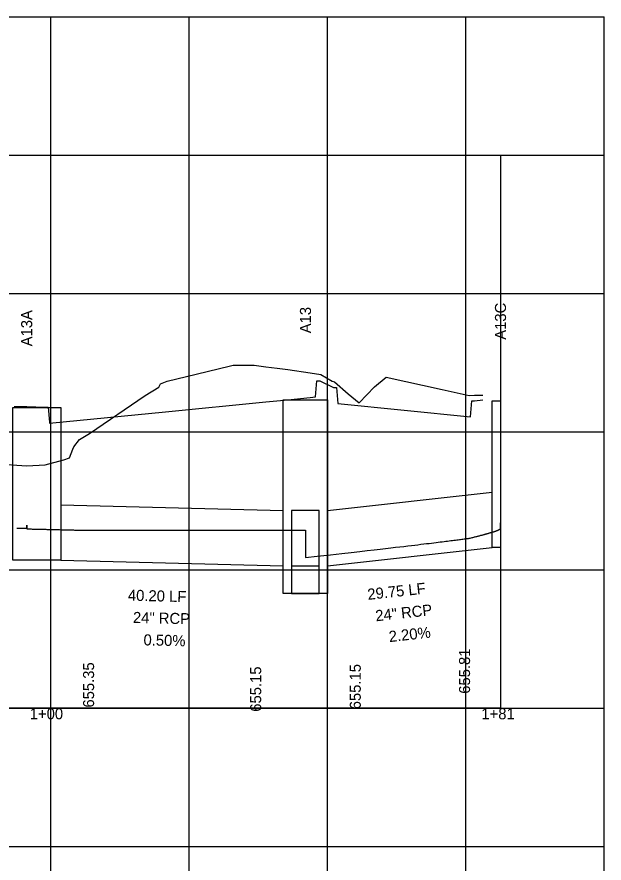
# Model space of a CAD drawing. Extents: x 2252703 to 2264864, y 13787568 to 13790989.
# Drawn here: x 2264657.5 to 2264763.7, y 13789162.9 to 13789315.9 of the extents above; entities that cross this region are included whole.
import ezdxf

# ---------------------------------------------------------------- set-up
doc = ezdxf.new("R2010")
doc.units = 0
for name, color, linetype in [('blank4', 7, 'Continuous'), ('BORD_grid_bottom_major_5int', 7, 'Continuous'), ('D_DRN_PROF_HGL', 7, 'Continuous'), ('D_PROF_1', 7, 'Continuous'), ('D_PROF_NOTES_1', 7, 'Continuous'), ('Default', 7, 'Continuous'), ('Drain_PipeInside', 7, 'Continuous'), ('E_Terrain', 7, 'Continuous'), ('Inlet', 7, 'Continuous'), ('z - Construction', 7, 'Continuous')]:
    doc.layers.add(name, color=color, linetype=linetype)

msp = doc.modelspace()

# ---------------------------------------------------------------- linework, layer by layer
at = {"layer": 'blank4'}
msp.add_lwpolyline([(2264563.67, 13789190.93), (2264563.67, 13789290.93), (2264744.95, 13789290.93), (2264744.95, 13789190.93)], close=True, dxfattribs=at)
at = {"layer": 'BORD_grid_bottom_major_5int'}
for p, q in [((2264413.67, 13789315.93), (2264763.67, 13789315.93)), ((2264663.67, 13789015.93), (2264663.67, 13789315.93)), ((2264688.67, 13789015.93), (2264688.67, 13789315.93)), ((2264713.67, 13789015.93), (2264713.67, 13789315.93)), ((2264738.67, 13789015.93), (2264738.67, 13789315.93)), ((2264763.67, 13789015.93), (2264763.67, 13789315.93)), ((2264413.67, 13789290.93), (2264763.67, 13789290.93)), ((2264413.67, 13789265.93), (2264763.67, 13789265.93)), ((2264413.67, 13789240.93), (2264763.67, 13789240.93)), ((2264413.67, 13789215.93), (2264763.67, 13789215.93)), ((2264413.67, 13789190.93), (2264763.67, 13789190.93)), ((2264413.67, 13789165.93), (2264763.67, 13789165.93))]:
    msp.add_line(p, q, dxfattribs=at)
at = {"layer": 'D_DRN_PROF_HGL'}
for p, q in [((2264659.31, 13789223.51), (2264659.31, 13789224.02)), ((2264709.7, 13789223.13), (2264709.7, 13789218.18))]:
    msp.add_line(p, q, dxfattribs=at)
for points in [[(2264657.53, 13789223.51), (2264657.73, 13789223.51), (2264657.93, 13789223.51), (2264658.12, 13789223.51), (2264658.32, 13789223.51), (2264658.52, 13789223.51), (2264658.72, 13789223.51), (2264658.92, 13789223.51), (2264659.12, 13789223.51), (2264659.31, 13789223.51)], [(2264659.31, 13789224.02), (2264659.31, 13789223.35), (2264659.35, 13789223.36), (2264659.54, 13789223.35), (2264659.73, 13789223.35), (2264659.92, 13789223.34), (2264660.11, 13789223.34), (2264660.3, 13789223.33), (2264660.49, 13789223.33), (2264660.68, 13789223.33), (2264660.87, 13789223.32), (2264661.06, 13789223.32), (2264661.25, 13789223.31), (2264661.44, 13789223.31), (2264661.63, 13789223.3), (2264661.82, 13789223.3), (2264662.02, 13789223.29), (2264662.21, 13789223.29), (2264662.4, 13789223.28), (2264662.59, 13789223.28), (2264662.78, 13789223.28), (2264662.97, 13789223.27), (2264663.16, 13789223.27), (2264663.35, 13789223.26), (2264663.55, 13789223.26), (2264663.74, 13789223.25), (2264663.93, 13789223.25), (2264664.12, 13789223.24), (2264664.31, 13789223.24), (2264664.51, 13789223.23), (2264664.7, 13789223.23), (2264664.89, 13789223.22), (2264665.08, 13789223.22), (2264665.27, 13789223.22), (2264665.47, 13789223.21), (2264665.66, 13789223.21), (2264665.85, 13789223.2), (2264666.04, 13789223.2), (2264666.24, 13789223.19), (2264666.43, 13789223.19), (2264666.62, 13789223.18), (2264666.81, 13789223.18), (2264667.01, 13789223.17), (2264667.2, 13789223.17), (2264667.39, 13789223.16), (2264667.58, 13789223.16), (2264667.78, 13789223.16), (2264667.97, 13789223.15), (2264668.16, 13789223.15), (2264668.36, 13789223.14), (2264668.55, 13789223.14), (2264668.74, 13789223.13), (2264668.93, 13789223.13), (2264669.13, 13789223.12), (2264669.32, 13789223.12), (2264669.51, 13789223.11), (2264669.71, 13789223.11), (2264669.9, 13789223.11), (2264670.09, 13789223.11), (2264670.29, 13789223.11), (2264670.48, 13789223.11), (2264670.68, 13789223.11), (2264670.87, 13789223.11), (2264671.06, 13789223.12), (2264671.26, 13789223.12), (2264671.45, 13789223.12), (2264671.64, 13789223.12), (2264671.84, 13789223.12), (2264672.03, 13789223.12), (2264672.23, 13789223.12), (2264672.42, 13789223.12), (2264672.61, 13789223.12), (2264672.81, 13789223.12), (2264673, 13789223.12), (2264673.2, 13789223.12), (2264673.39, 13789223.12), (2264673.58, 13789223.12), (2264673.78, 13789223.12), (2264673.97, 13789223.12), (2264674.17, 13789223.12), (2264674.36, 13789223.12), (2264674.56, 13789223.12), (2264674.75, 13789223.12), (2264674.95, 13789223.12), (2264675.14, 13789223.12), (2264675.34, 13789223.12), (2264675.53, 13789223.12), (2264675.72, 13789223.12), (2264675.92, 13789223.12), (2264676.11, 13789223.12), (2264676.31, 13789223.12), (2264676.5, 13789223.12), (2264676.7, 13789223.12), (2264676.89, 13789223.12), (2264677.09, 13789223.12), (2264677.28, 13789223.12), (2264677.48, 13789223.12), (2264677.67, 13789223.12), (2264677.87, 13789223.12), (2264678.07, 13789223.12), (2264678.26, 13789223.12), (2264678.46, 13789223.12), (2264678.65, 13789223.12), (2264678.85, 13789223.12), (2264679.04, 13789223.12), (2264679.24, 13789223.12), (2264679.43, 13789223.12), (2264679.63, 13789223.12), (2264679.82, 13789223.12), (2264680.02, 13789223.12), (2264680.22, 13789223.12), (2264680.41, 13789223.12), (2264680.61, 13789223.12), (2264680.8, 13789223.12), (2264681, 13789223.12), (2264681.19, 13789223.12), (2264681.39, 13789223.12), (2264681.59, 13789223.12), (2264681.78, 13789223.12), (2264681.98, 13789223.12), (2264682.17, 13789223.12), (2264682.37, 13789223.12), (2264682.57, 13789223.12), (2264682.76, 13789223.12), (2264682.96, 13789223.12), (2264683.15, 13789223.12), (2264683.35, 13789223.12), (2264683.55, 13789223.12), (2264683.74, 13789223.12), (2264683.94, 13789223.12), (2264684.14, 13789223.12), (2264684.33, 13789223.12), (2264684.53, 13789223.12), (2264684.73, 13789223.12), (2264684.92, 13789223.12), (2264685.12, 13789223.12), (2264685.32, 13789223.12), (2264685.51, 13789223.12), (2264685.71, 13789223.12), (2264685.91, 13789223.12), (2264686.1, 13789223.12), (2264686.3, 13789223.12), (2264686.5, 13789223.12), (2264686.69, 13789223.12), (2264686.89, 13789223.12), (2264687.09, 13789223.12), (2264687.28, 13789223.12), (2264687.48, 13789223.12), (2264687.68, 13789223.12), (2264687.87, 13789223.12), (2264688.07, 13789223.12), (2264688.27, 13789223.12), (2264688.46, 13789223.12), (2264688.66, 13789223.12), (2264688.86, 13789223.12), (2264689.06, 13789223.12), (2264689.25, 13789223.12), (2264689.45, 13789223.13), (2264689.65, 13789223.13), (2264689.84, 13789223.13), (2264690.04, 13789223.13), (2264690.24, 13789223.13), (2264690.44, 13789223.13), (2264690.63, 13789223.13), (2264690.83, 13789223.13), (2264691.03, 13789223.13), (2264691.23, 13789223.13), (2264691.42, 13789223.13), (2264691.62, 13789223.13), (2264691.82, 13789223.13), (2264692.02, 13789223.13), (2264692.21, 13789223.13), (2264692.41, 13789223.13), (2264692.61, 13789223.13), (2264692.81, 13789223.13), (2264693.01, 13789223.13), (2264693.2, 13789223.13), (2264693.4, 13789223.13), (2264693.6, 13789223.13), (2264693.8, 13789223.13), (2264693.99, 13789223.13), (2264694.19, 13789223.13), (2264694.39, 13789223.13), (2264694.59, 13789223.13), (2264694.79, 13789223.13), (2264694.98, 13789223.13), (2264695.18, 13789223.13), (2264695.38, 13789223.13), (2264695.58, 13789223.13), (2264695.78, 13789223.13), (2264695.97, 13789223.13), (2264696.17, 13789223.13), (2264696.37, 13789223.13), (2264696.57, 13789223.13), (2264696.77, 13789223.13), (2264696.97, 13789223.13), (2264697.16, 13789223.13), (2264697.36, 13789223.13), (2264697.56, 13789223.13), (2264697.76, 13789223.13), (2264697.96, 13789223.13), (2264698.15, 13789223.13), (2264698.35, 13789223.13), (2264698.55, 13789223.13), (2264698.75, 13789223.13), (2264698.95, 13789223.13), (2264699.15, 13789223.13), (2264699.35, 13789223.13), (2264699.54, 13789223.13), (2264699.74, 13789223.13), (2264699.94, 13789223.13), (2264700.14, 13789223.13), (2264700.34, 13789223.13), (2264700.54, 13789223.13), (2264700.74, 13789223.13), (2264700.93, 13789223.13), (2264701.13, 13789223.13), (2264701.33, 13789223.13), (2264701.53, 13789223.13), (2264701.73, 13789223.13), (2264701.93, 13789223.13), (2264702.13, 13789223.13), (2264702.33, 13789223.13), (2264702.53, 13789223.13), (2264702.72, 13789223.13), (2264702.92, 13789223.13), (2264703.12, 13789223.13), (2264703.32, 13789223.13), (2264703.52, 13789223.13), (2264703.72, 13789223.13), (2264703.92, 13789223.13), (2264704.12, 13789223.13), (2264704.32, 13789223.13), (2264704.52, 13789223.13), (2264704.71, 13789223.13), (2264704.91, 13789223.13), (2264705.11, 13789223.13), (2264705.31, 13789223.13), (2264705.51, 13789223.13), (2264705.71, 13789223.13), (2264705.91, 13789223.13), (2264706.11, 13789223.13), (2264706.31, 13789223.13), (2264706.51, 13789223.13), (2264706.71, 13789223.13), (2264706.91, 13789223.13), (2264707.11, 13789223.13), (2264707.3, 13789223.13), (2264707.5, 13789223.13), (2264707.7, 13789223.13), (2264707.9, 13789223.13), (2264708.1, 13789223.13), (2264708.3, 13789223.13), (2264708.5, 13789223.13), (2264708.7, 13789223.13), (2264708.9, 13789223.13), (2264709.1, 13789223.13), (2264709.3, 13789223.13), (2264709.5, 13789223.13), (2264709.7, 13789223.13)], [(2264709.7, 13789218.18), (2264711.84, 13789218.42), (2264714.24, 13789218.69), (2264716.26, 13789218.92), (2264717.99, 13789219.11), (2264719.52, 13789219.29), (2264720.87, 13789219.44), (2264722.09, 13789219.58), (2264723.19, 13789219.7), (2264724.19, 13789219.82), (2264725.12, 13789219.93), (2264725.97, 13789220.03), (2264726.76, 13789220.12), (2264727.5, 13789220.2), (2264728.19, 13789220.29), (2264728.84, 13789220.36), (2264729.45, 13789220.43), (2264730.02, 13789220.5), (2264730.57, 13789220.57), (2264731.08, 13789220.63), (2264731.57, 13789220.69), (2264732.03, 13789220.74), (2264732.48, 13789220.8), (2264732.9, 13789220.85), (2264733.3, 13789220.9), (2264733.69, 13789220.94), (2264734.06, 13789220.99), (2264734.41, 13789221.03), (2264734.75, 13789221.08), (2264735.08, 13789221.12), (2264735.39, 13789221.16), (2264735.69, 13789221.2), (2264735.98, 13789221.23), (2264736.26, 13789221.27), (2264736.53, 13789221.3), (2264736.79, 13789221.34), (2264737.04, 13789221.37), (2264737.28, 13789221.4), (2264737.52, 13789221.43), (2264737.74, 13789221.46), (2264737.96, 13789221.49), (2264738.17, 13789221.52), (2264738.38, 13789221.55), (2264738.58, 13789221.57), (2264738.77, 13789221.6), (2264738.96, 13789221.62), (2264739.14, 13789221.65), (2264739.31, 13789221.67), (2264739.48, 13789221.7), (2264739.65, 13789221.74), (2264739.81, 13789221.78), (2264739.96, 13789221.82), (2264740.12, 13789221.86), (2264740.26, 13789221.9), (2264740.4, 13789221.93), (2264740.54, 13789221.97), (2264740.68, 13789222), (2264740.81, 13789222.04), (2264740.94, 13789222.07), (2264741.06, 13789222.1), (2264741.18, 13789222.13), (2264741.3, 13789222.17), (2264741.41, 13789222.2), (2264741.52, 13789222.22), (2264741.63, 13789222.25), (2264741.74, 13789222.28), (2264741.84, 13789222.31), (2264741.94, 13789222.34), (2264742.03, 13789222.36), (2264742.13, 13789222.39), (2264742.22, 13789222.41), (2264742.31, 13789222.44), (2264742.4, 13789222.46), (2264742.48, 13789222.49), (2264742.56, 13789222.51), (2264742.64, 13789222.53), (2264742.72, 13789222.55), (2264742.8, 13789222.58), (2264742.87, 13789222.6), (2264742.94, 13789222.62), (2264743.01, 13789222.64), (2264743.08, 13789222.66), (2264743.15, 13789222.68), (2264743.21, 13789222.7), (2264743.28, 13789222.72), (2264743.34, 13789222.73), (2264743.4, 13789222.75), (2264743.45, 13789222.77), (2264743.51, 13789222.79), (2264743.57, 13789222.8), (2264743.62, 13789222.82), (2264743.67, 13789222.84), (2264743.72, 13789222.85), (2264743.77, 13789222.87), (2264743.82, 13789222.88), (2264743.86, 13789222.9), (2264743.91, 13789222.91), (2264743.95, 13789222.93), (2264744, 13789222.94), (2264744.04, 13789222.96), (2264744.08, 13789222.97), (2264744.12, 13789222.99), (2264744.15, 13789223), (2264744.19, 13789223.01), (2264744.23, 13789223.02), (2264744.26, 13789223.04), (2264744.29, 13789223.05), (2264744.33, 13789223.06), (2264744.36, 13789223.07), (2264744.39, 13789223.08), (2264744.42, 13789223.1), (2264744.44, 13789223.11), (2264744.47, 13789223.12), (2264744.5, 13789223.13), (2264744.52, 13789223.14), (2264744.55, 13789223.15), (2264744.57, 13789223.16), (2264744.59, 13789223.17), (2264744.62, 13789223.18), (2264744.64, 13789223.19), (2264744.66, 13789223.2), (2264744.68, 13789223.21), (2264744.7, 13789223.22), (2264744.71, 13789223.23), (2264744.73, 13789223.24), (2264744.75, 13789223.24), (2264744.76, 13789223.25), (2264744.78, 13789223.26), (2264744.79, 13789223.27), (2264744.81, 13789223.28), (2264744.82, 13789223.29), (2264744.83, 13789223.29), (2264744.84, 13789223.3), (2264744.85, 13789223.31), (2264744.86, 13789223.31), (2264744.87, 13789223.32), (2264744.88, 13789223.33), (2264744.89, 13789223.34), (2264744.9, 13789223.34), (2264744.91, 13789223.35), (2264744.91, 13789223.36), (2264744.92, 13789223.36), (2264744.92, 13789223.37), (2264744.93, 13789223.37), (2264744.93, 13789223.38), (2264744.94, 13789223.39), (2264744.94, 13789223.39), (2264744.94, 13789223.4), (2264744.95, 13789223.4), (2264744.95, 13789223.41), (2264744.95, 13789223.41), (2264744.95, 13789223.42), (2264744.95, 13789223.42), (2264744.95, 13789224.43)]]:
    msp.add_lwpolyline(points, dxfattribs=at)
at = {"layer": 'D_PROF_1'}
msp.add_lwpolyline([(2264657.07, 13789245.51), (2264658.75, 13789245.48), (2264659.31, 13789245.47), (2264659.31, 13789245.47), (2264662.67, 13789245.38), (2264662.67, 13789245.38), (2264662.67, 13789245.38), (2264662.69, 13789245.38), (2264663.19, 13789245.37), (2264663.41, 13789242.63), (2264663.42, 13789242.46), (2264684.41, 13789244.52), (2264702.53, 13789246.31), (2264702.53, 13789246.31), (2264702.53, 13789246.31), (2264706.53, 13789246.71), (2264706.53, 13789246.71), (2264710.53, 13789247.11), (2264710.53, 13789247.11), (2264711.53, 13789247.21), (2264711.76, 13789250.12), (2264712.28, 13789250.12), (2264714.78, 13789248.92), (2264715.3, 13789248.92), (2264715.53, 13789246.01), (2264739.53, 13789243.61), (2264739.76, 13789246.52), (2264740.28, 13789246.52), (2264740.28, 13789246.52), (2264740.28, 13789246.52), (2264741.78, 13789246.67)], dxfattribs=at)
at = {"layer": 'Default'}
msp.add_line((2264663.67, 13789190.93), (2264663.67, 13789290.93), dxfattribs=at)
at = {"layer": 'Drain_PipeInside'}
for p, q in [((2264713.7, 13789226.7), (2264743.45, 13789229.97)), ((2264665.5, 13789227.68), (2264705.7, 13789226.68)), ((2264713.7, 13789216.7), (2264743.45, 13789219.97)), ((2264665.5, 13789217.68), (2264705.7, 13789216.68))]:
    msp.add_line(p, q, dxfattribs=at)
for points in [[(2264707.2, 13789211.7), (2264712.2, 13789211.7), (2264712.2, 13789226.7), (2264707.2, 13789226.7)], [(2264707.2, 13789216.68), (2264712.2, 13789216.68), (2264712.2, 13789226.68), (2264707.2, 13789226.68)]]:
    msp.add_lwpolyline(points, close=True, dxfattribs=at)
at = {"layer": 'E_Terrain'}
msp.add_lwpolyline([(2264653.81, 13789235.15), (2264659.31, 13789234.79), (2264659.31, 13789234.79), (2264662.67, 13789234.97), (2264662.67, 13789234.97), (2264666, 13789235.83), (2264667.06, 13789236.19), (2264667.64, 13789237.79), (2264667.82, 13789238.19), (2264668.85, 13789239.51), (2264670.66, 13789240.58), (2264680.73, 13789247.47), (2264683.22, 13789249), (2264683.5, 13789249.56), (2264684.68, 13789250.04), (2264688.21, 13789250.9), (2264695.9, 13789252.8), (2264696.66, 13789252.95), (2264700.43, 13789252.94), (2264702.53, 13789252.69), (2264702.53, 13789252.69), (2264704.58, 13789252.44), (2264706.53, 13789252.15), (2264706.53, 13789252.15), (2264710.53, 13789251.57), (2264710.53, 13789251.57), (2264712.45, 13789251.29), (2264714.5, 13789250.08), (2264714.93, 13789249.97), (2264717.44, 13789247.75), (2264719.41, 13789246.17), (2264722.15, 13789249.06), (2264724.26, 13789250.82), (2264734.42, 13789248.55), (2264739.29, 13789247.5), (2264740.28, 13789247.51), (2264740.28, 13789247.51), (2264741.78, 13789247.53)], dxfattribs=at)
at = {"layer": 'Inlet'}
for points in [[(2264705.7, 13789246.71), (2264713.7, 13789246.71), (2264713.7, 13789211.7), (2264705.7, 13789211.7)], [(2264743.45, 13789246.52), (2264744.95, 13789246.52), (2264744.95, 13789219.97), (2264743.45, 13789219.97)], [(2264656.81, 13789245.32), (2264665.5, 13789245.32), (2264665.5, 13789217.68), (2264656.81, 13789217.68)]]:
    msp.add_lwpolyline(points, close=True, dxfattribs=at)
at = {"layer": 'z - Construction'}
for p, q in [((2264563.67, 13789265.93), (2264744.95, 13789265.93)), ((2264563.67, 13789240.93), (2264744.95, 13789240.93)), ((2264563.67, 13789215.93), (2264744.95, 13789215.93))]:
    msp.add_line(p, q, dxfattribs=at)

# ---------------------------------------------------------------- texts
at = {"layer": 'D_PROF_NOTES_1'}
for s, rotation, p in [('A13A', 90, (2264660.31, 13789256.37)), ('A13', 90, (2264710.7, 13789258.73)), ('A13C', 90, (2264745.95, 13789257.56)), ('40.20 LF', 358.5679, (2264677.59, 13789210.38)), ('29.75 LF', 6.2773, (2264721.01, 13789210.51)), ('24" RCP', 6.2773, (2264722.45, 13789206.64)), ('24" RCP', 358.5679, (2264678.5, 13789206.36)), ('2.20%', 6.2773, (2264724.88, 13789202.88)), ('0.50%', 358.5679, (2264680.41, 13789202.31)), ('655.81', 90, (2264739.45, 13789193.55)), ('655.35', 90, (2264671.5, 13789191.05)), ('655.15', 90, (2264719.7, 13789190.74)), ('655.15', 90, (2264701.7, 13789190.3))]:
    msp.add_text(s, height=2, rotation=rotation, dxfattribs=at).set_placement(p)
at = {"layer": 'Default'}
for s, p in [('1+00', (2264659.87, 13789188.93)), ('1+81', (2264741.5, 13789188.93))]:
    msp.add_text(s, height=2, dxfattribs=at).set_placement(p)

doc.saveas('drawing.dxf')
